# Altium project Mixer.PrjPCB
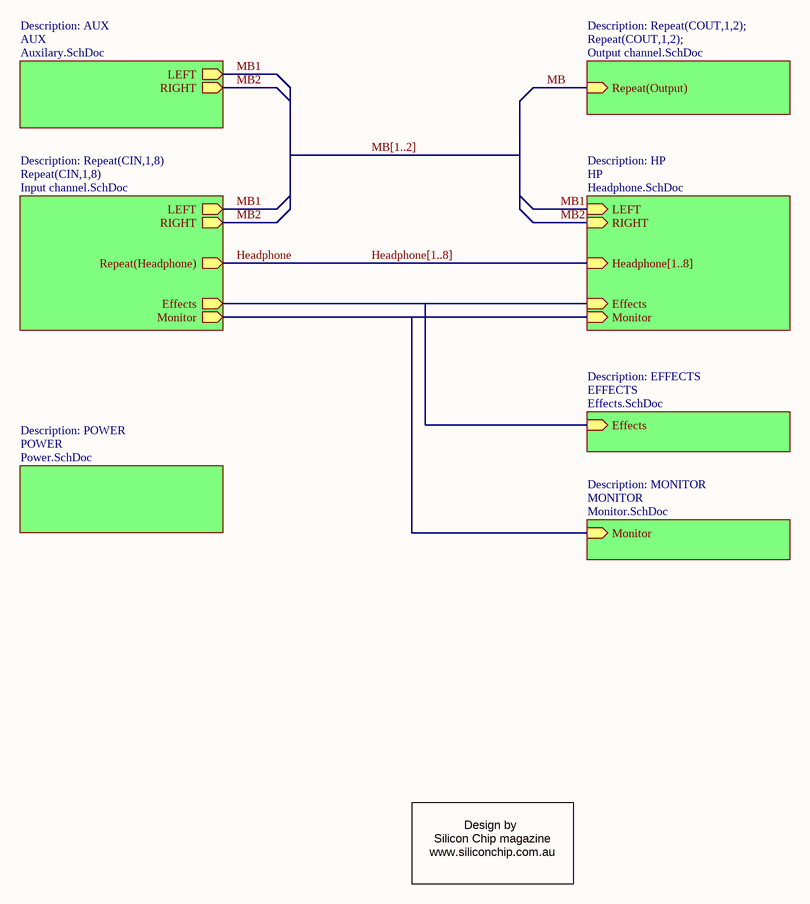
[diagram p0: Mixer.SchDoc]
8 sheets, 523 parts. Net scope: hierarchical (ports join the sheet entries above them; power ports are global).
Board files: Mixer_Blank.PCBDOC, Mixer_Loaded.PCBDOC, Mixer_Placed.PCBDOC, Mixer_RoomsOnly.PCBDOC, Mixer_Routed.PCBDOC
Sheets:
  Mixer.SchDoc
    AUX = Auxilary.SchDoc
    CIN1 = Input channel.SchDoc
    CIN2 = Input channel.SchDoc
    CIN3 = Input channel.SchDoc
    CIN4 = Input channel.SchDoc
    CIN5 = Input channel.SchDoc
    CIN6 = Input channel.SchDoc
    CIN7 = Input channel.SchDoc
    CIN8 = Input channel.SchDoc
    MONITOR = Monitor.SchDoc
    EFFECTS = Effects.SchDoc
    HP = Headphone.SchDoc
    POWER = Power.SchDoc
    Repeat(COUT,1,2); = Output channel.SchDoc

## Sheet Mixer.SchDoc
size A4; Organization: Altium Limited; Address1: L3, 12a Rodborough Rd; Address2: Frenchs Forest; Address3: NSW; Address4: Australia 2086; DocumentNumber: 5; SheetNumber: 5; SheetTotal: 8

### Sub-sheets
AUX = Auxilary.SchDoc: LEFT, RIGHT  | Description: AUX
EFFECTS = Effects.SchDoc: Effects  | Description: EFFECTS
HP = Headphone.SchDoc: Headphone[1..8] (in), Monitor, Effects, LEFT, RIGHT  | Description: HP
MONITOR = Monitor.SchDoc: Monitor  | Description: MONITOR
POWER = Power.SchDoc: no entries  | Description: POWER
Repeat(CIN,1,8) = Input channel.SchDoc: Monitor, LEFT, Repeat(Headphone) (out), Effects, RIGHT  | Description: Repeat(CIN,1,8)
Repeat(COUT,1,2); = Output channel.SchDoc: Repeat(Output)  | Description: Repeat(COUT,1,2);

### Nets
MB1: sheet AUX/LEFT, sheet Repeat(CIN,1,8)/LEFT, sheet HP/LEFT
MB2: sheet AUX/RIGHT, sheet Repeat(CIN,1,8)/RIGHT, sheet HP/RIGHT
NetR29_1: sheet Repeat(CIN,1,8)/Monitor, sheet MONITOR/Monitor, sheet HP/Monitor
NetR33_1: sheet Repeat(CIN,1,8)/Effects, sheet EFFECTS/Effects, sheet HP/Effects

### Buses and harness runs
bus Headphone[1..8] = sheet HP/Headphone[1..8]
bus MB[1..2]

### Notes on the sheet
- Design by
  Silicon Chip magazine
  www.siliconchip.com.au

## Sheet Auxilary.SchDoc
size A4; Organization: Altium Limited; Address1: L3, 12a Rodborough Rd; Address2: Frenchs Forest; Address3: NSW; Address4: Australia 2086; DocumentNumber: 1; SheetNumber: 1; SheetTotal: 8
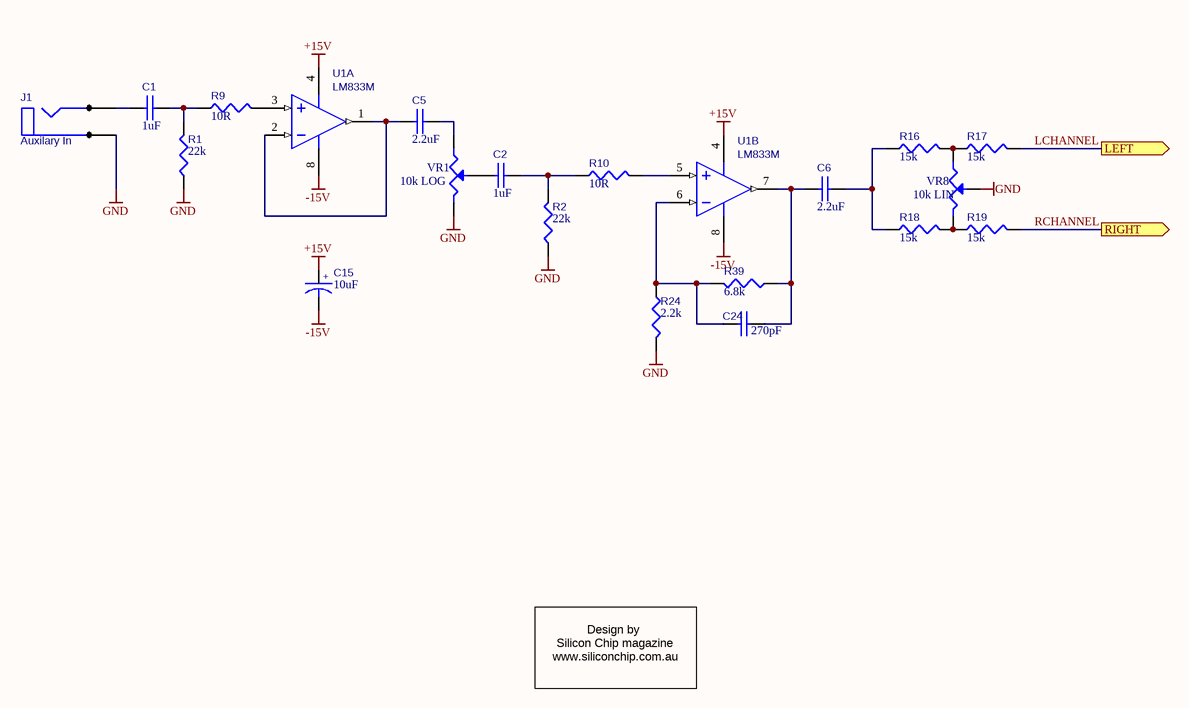
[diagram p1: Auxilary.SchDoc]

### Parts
C1  1uF  [RB.2/.4-NP]
C2  1uF  [RB.2/.4-NP]
C5  2.2uF  [RB.2/.4-NP]
C6  2.2uF  [RB.2/.4-NP]
C15  10uF  [RB.2/.4]
C24  270pF  [RAD0.2]
J1  Auxilary In  [JACK-6.25MM]
R1  22k  [AXIAL0.4]
R2  22k  [AXIAL0.4]
R9  10R  [AXIAL0.4]
R10  10R  [AXIAL0.4]
R16  15k  [AXIAL0.4]
R17  15k  [AXIAL0.4]
R18  15k  [AXIAL0.4]
R19  15k  [AXIAL0.4]
R24  2.2k  [AXIAL0.4]
R39  6.8k  [AXIAL0.4]
U1  LM833M  [DIP8]  (parts A,B of 2)
VR1  10k LOG  [POT - 24MM]
VR8  10k LIN  [POT - 24MM]

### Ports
LEFT (out), RIGHT (out)

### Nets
+15V: C15.1 U1.4(V-)
-15V: C15.2 U1.8(V+)
GND: J1.3(C) R1.1 R2.1 R24.2 VR1.3 VR8.2(W)
LCHANNEL: R17.2 ; port LEFT  [project net MB1]
RCHANNEL: R19.2 ; port RIGHT  [project net MB2]
NetC1_1: C1.1 J1.1(A)
NetC1_2: C1.2 R1.2 R9.1
NetC2_1: C2.1 VR1.2(W)
NetC2_2: C2.2 R2.2 R10.1
NetC5_1: C5.1 U1.1(OUT1) U1.2(IN1-)
NetC5_2: C5.2 VR1.1
NetC6_1: C6.1 C24.2 R39.1 U1.7(OUT2)
NetC6_2: C6.2 R16.1 R18.1
NetC24_1: C24.1 R24.1 R39.2 U1.6(IN2-)
NetR9_2: R9.2 U1.3(IN1+)
NetR10_2: R10.2 U1.5(IN2+)
NetR16_2: R16.2 R17.1 VR8.1
NetR18_2: R18.2 R19.1 VR8.3

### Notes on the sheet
- Design by
  Silicon Chip magazine
  www.siliconchip.com.au

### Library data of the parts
C1 C2 C5 C6 C24 = CAP: Capacitor
C15 = CAPACITOR POL: Bi-Polar Capacitor
J1 = PHONEJACK MONO
R1 R2 R9 R10 R16-R19 R24 R39 = RES1: Resistor
U1 = LM833M: Fast Settling Dual Operational Amplifier
VR1 VR8 = POT1: Potentiometer

## Sheet Input channel.SchDoc
size A4; Organization: Altium Limited; Address1: L3, 12a Rodborough Rd; Address2: Frenchs Forest; Address3: NSW; Address4: Australia 2086; DocumentNumber: 4; SheetNumber: 4; SheetTotal: 8
Used 8 times, as channels CIN1, CIN2, CIN3, CIN4, CIN5, CIN6, CIN7, CIN8. Parts and nets are listed once, with the designators drawn on the sheet.
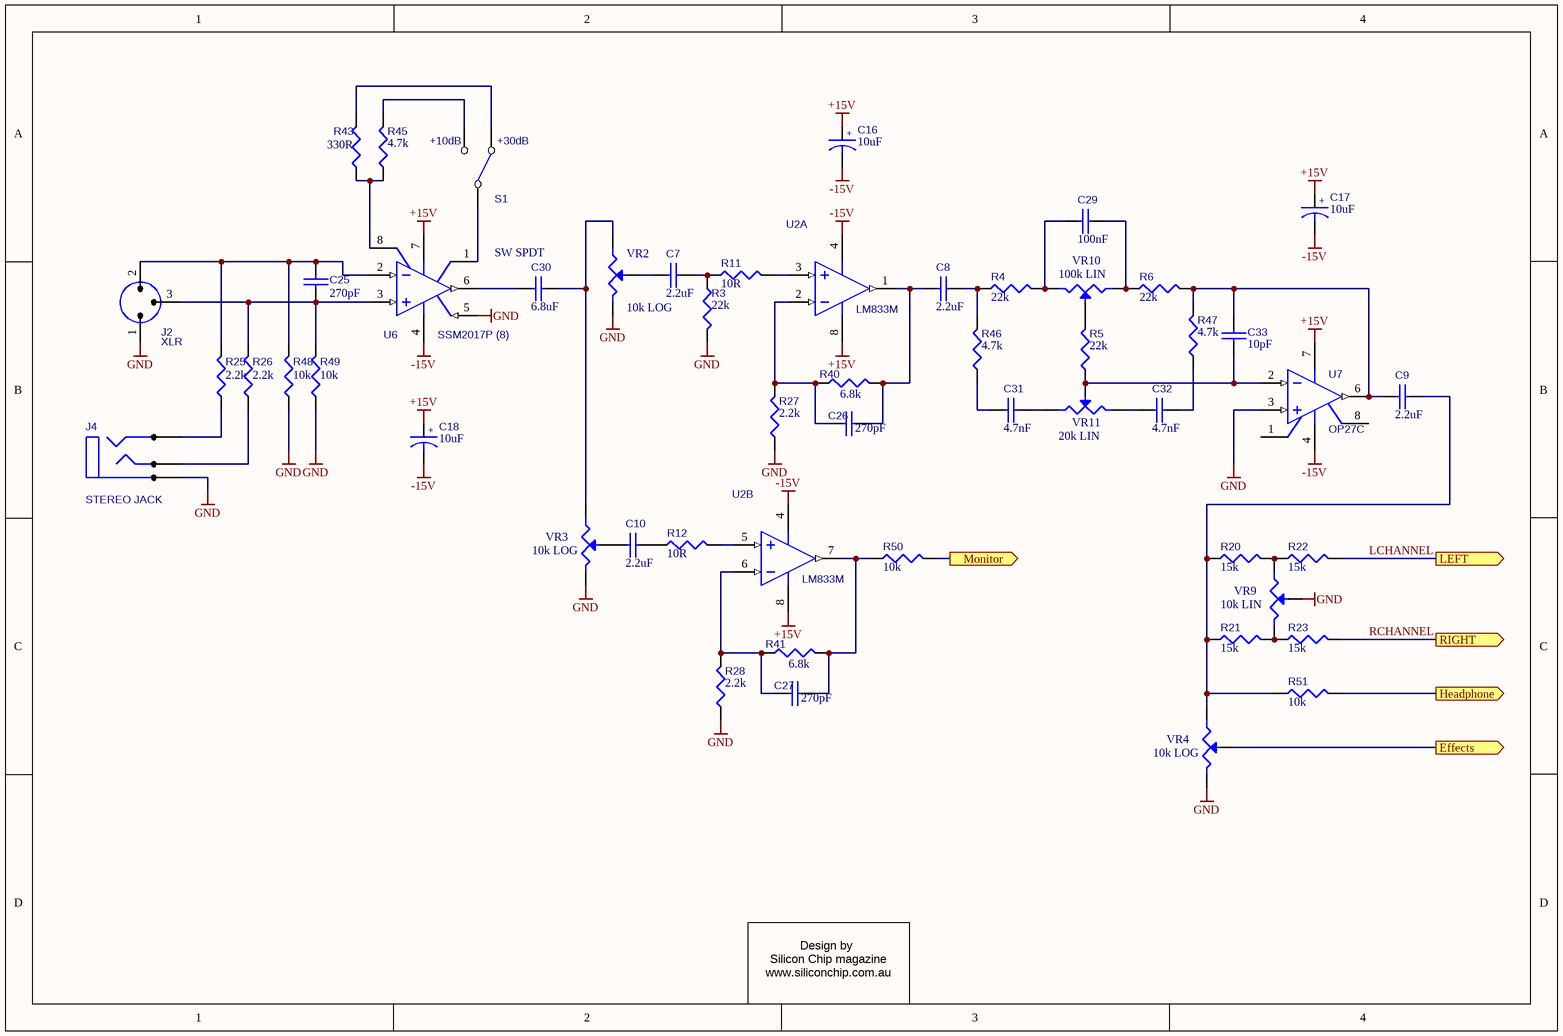
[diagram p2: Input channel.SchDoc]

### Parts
C7  2.2uF  [RB.2/.4-NP]
C8  2.2uF  [RB.2/.4-NP]
C9  2.2uF  [RB.2/.4-NP]
C10  2.2uF  [RB.2/.4-NP]
C16  10uF  [RB.2/.4]
C17  10uF  [RB.2/.4]
C18  10uF  [RB.2/.4]
C25  270pF  [RAD0.2]
C26  270pF  [RAD0.2]
C27  270pF  [RAD0.2]
C29  100nF  [RAD0.2]
C30  6.8uF  [RB.2/.4-NP]
C31  4.7nF  [RAD0.2]
C32  4.7nF  [RAD0.2]
C33  10pF  [RAD0.2]
J2  XLR  [XLR-FEMALE]
J4  STEREO JACK  [JACK-6.25MM]
R3  22k  [AXIAL0.4]
R4  22k  [AXIAL0.4]
R5  22k  [AXIAL0.4]
R6  22k  [AXIAL0.4]
R11  10R  [AXIAL0.4]
R12  10R  [AXIAL0.4]
R20  15k  [AXIAL0.4]
R21  15k  [AXIAL0.4]
R22  15k  [AXIAL0.4]
R23  15k  [AXIAL0.4]
R25  2.2k  [AXIAL0.4]
R26  2.2k  [AXIAL0.4]
R27  2.2k  [AXIAL0.4]
R28  2.2k  [AXIAL0.4]
R40  6.8k  [AXIAL0.4]
R41  6.8k  [AXIAL0.4]
R43  330R  [AXIAL0.4]
R45  4.7k  [AXIAL0.4]
R46  4.7k  [AXIAL0.4]
R47  4.7k  [AXIAL0.4]
R48  10k  [AXIAL0.4]
R49  10k  [AXIAL0.4]
R50  10k  [AXIAL0.4]
R51  10k  [AXIAL0.4]
S1  SW SPDT  [SW-SPDT]
U2  LM833M  [DIP8]  (parts A,B of 2)
U6  SSM2017P (8)  [DIP8]
U7  OP27C  [DIP8]
VR2  10k LOG  [POT - 24MM]
VR3  10k LOG  [POT - 24MM]
VR4  10k LOG  [POT - 24MM]
VR9  10k LIN  [POT - 24MM]
VR10  100k LIN  [POT - 24MM]
VR11  20k LIN  [POT - 24MM]

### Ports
Effects (out), Headphone (out), LEFT (out), Monitor (out), RIGHT (out)

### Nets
+15V: C16.1 C17.1 C18.1 U2.8(V+) U6.7(V+) U7.7(V+)
-15V: C16.2 C17.2 C18.2 U2.4(V-) U6.4(V-) U7.4(V-)
GND: J2.1 J4.3(C) R3.2 R27.1 R28.1 R48.1 R49.1 U6.5(REF) U7.3(+IN) VR2.3 VR3.3 VR4.3 VR9.2(W)
Effects: VR4.2(W) ; port Effects
Headphone: R51.2 ; port Headphone
LCHANNEL: R22.2 ; port LEFT
Monitor: R50.2 ; port Monitor
RCHANNEL: R23.2 ; port RIGHT
NetC7_1: C7.1 VR2.2(W)
NetC7_2: C7.2 R3.1 R11.1
NetC8_1: C8.1 C26.2 R40.2 U2.1(OUT1)
NetC8_2: C8.2 R4.1 R46.2
NetC9_1: C9.1 C33.2 R6.2 R47.2 U7.6(OUT)
NetC9_2: C9.2 R20.1 R21.1 R51.1 VR4.1
NetC10_1: C10.1 VR3.2(W)
NetC10_2: C10.2 R12.1
NetC25_1: C25.1 J2.2 R25.2 R48.2 U6.2(IN-)
NetC25_2: C25.2 J2.3 R26.2 R49.2 U6.3(IN+)
NetC26_1: C26.1 R27.2 R40.1 U2.2(IN1-)
NetC27_1: C27.1 R28.2 R41.1 U2.6(IN2-)
NetC27_2: C27.2 R41.2 R50.1 U2.7(OUT2)
NetC29_1: C29.1 R4.2 VR10.3
NetC29_2: C29.2 R6.1 VR10.1
NetC30_1: C30.1 U6.6(OUT)
NetC30_2: C30.2 VR2.1 VR3.1
NetC31_1: C31.1 R46.1
NetC31_2: C31.2 VR11.1
NetC32_1: C32.1 VR11.3
NetC32_2: C32.2 R47.1
NetC33_1: C33.1 R5.1 U7.2(-IN) VR11.2(W)
NetJ4_1: J4.1(A) R25.1
NetJ4_2: J4.2(B) R26.1
NetR5_2: R5.2 VR10.2(W)
NetR11_2: R11.2 U2.3(IN1+)
NetR12_2: R12.2 U2.5(IN2+)
NetR20_2: R20.2 R22.1 VR9.1
NetR21_2: R21.2 R23.1 VR9.3
NetR43_1: R43.1 R45.1 U6.8(RG2)
NetR43_2: R43.2 S1.2(NC)
NetR45_2: R45.2 S1.3(NO)
NetS1_1: S1.1(COMMON) U6.1(RG1)

Not connected (* = marked no-connect by the designer): U7 1(TRIM) 8(TRIM)

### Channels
CIN1: designators end in _CIN1; ports Effects=NetR33_1 Headphone=Headphone1 LEFT=MB1 Monitor=NetR29_1 RIGHT=MB2
CIN2: designators end in _CIN2; ports Effects=NetR33_1 Headphone=Headphone2 LEFT=MB1 Monitor=NetR29_1 RIGHT=MB2
CIN3: designators end in _CIN3; ports Effects=NetR33_1 Headphone=Headphone3 LEFT=MB1 Monitor=NetR29_1 RIGHT=MB2
CIN4: designators end in _CIN4; ports Effects=NetR33_1 Headphone=Headphone4 LEFT=MB1 Monitor=NetR29_1 RIGHT=MB2
CIN5: designators end in _CIN5; ports Effects=NetR33_1 Headphone=Headphone5 LEFT=MB1 Monitor=NetR29_1 RIGHT=MB2
CIN6: designators end in _CIN6; ports Effects=NetR33_1 Headphone=Headphone6 LEFT=MB1 Monitor=NetR29_1 RIGHT=MB2
CIN7: designators end in _CIN7; ports Effects=NetR33_1 Headphone=Headphone7 LEFT=MB1 Monitor=NetR29_1 RIGHT=MB2
CIN8: designators end in _CIN8; ports Effects=NetR33_1 Headphone=Headphone8 LEFT=MB1 Monitor=NetR29_1 RIGHT=MB2

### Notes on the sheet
- (near S1) +10dB
- (near S1) +30dB
- Design by
  Silicon Chip magazine
  www.siliconchip.com.au

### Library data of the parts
C7-C10 C25-C27 C29-C33 = CAP: Capacitor
C16-C18 = CAPACITOR POL: Bi-Polar Capacitor
J2 = XLR: XLR connector, PCB mounted
J4 = PHONEJACK STEREO
R3-R6 R11 R12 R20-R23 R25-R28 R40 R41 R43 R45-R51 = RES1: Resistor
U2 = LM833M: Fast Settling Dual Operational Amplifier
U6 = SSM2017P (8): Self-Contained Audio Preamplifier
U7 = OP27C: Low Noise, High Speed Precision Operational Amplifier
VR2-VR4 VR9-VR11 = POT1: Potentiometer

## Sheet Monitor.SchDoc
size A4; Organization: Altium Limited; Address1: L3, 12a Rodborough Rd; Address2: Frenchs Forest; Address3: NSW; Address4: Australia 2086; DocumentNumber: 6; SheetNumber: 6; SheetTotal: 8
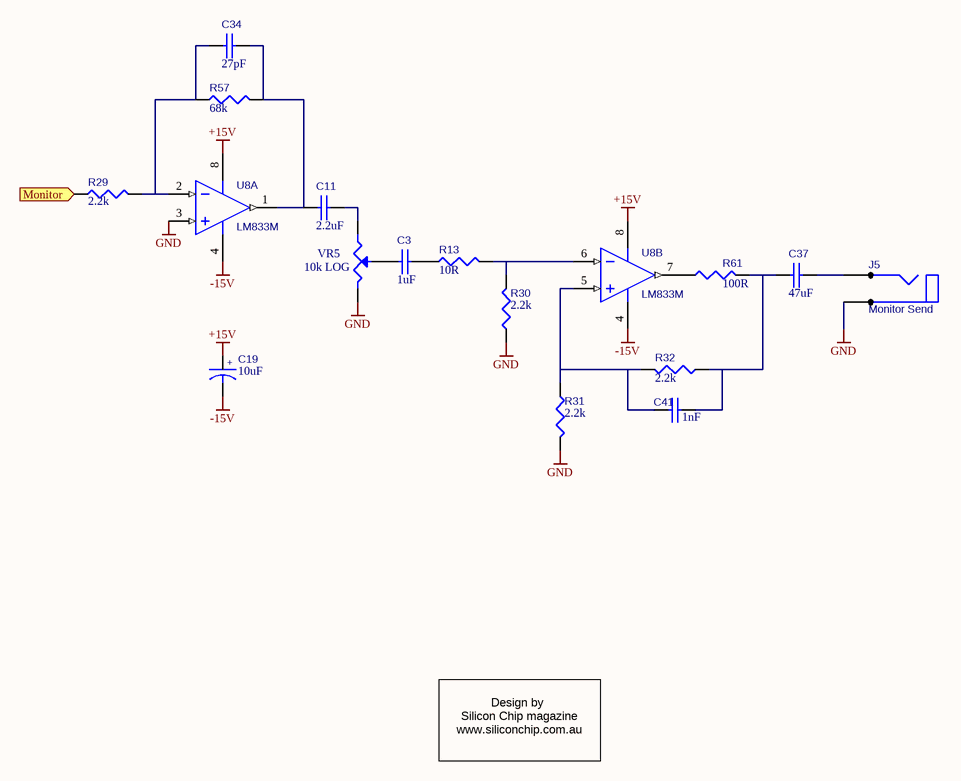
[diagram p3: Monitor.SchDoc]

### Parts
C3  1uF  [RB.2/.4-NP]
C11  2.2uF  [RB.2/.4-NP]
C19  10uF  [RB.2/.4]
C34  27pF  [RAD0.2]
C37  47uF  [RB.2/.4-NP]
C41  1nF  [RAD0.2]
J5  Monitor Send  [JACK-6.25MM]
R13  10R  [AXIAL0.4]
R29  2.2k  [AXIAL0.4]
R30  2.2k  [AXIAL0.4]
R31  2.2k  [AXIAL0.4]
R32  2.2k  [AXIAL0.4]
R57  68k  [AXIAL0.4]
R61  100R  [AXIAL0.4]
U8  LM833M  [DIP8]  (parts A,B of 2)
VR5  10k LOG  [POT - 24MM]

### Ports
Monitor (in)

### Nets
+15V: C19.1 U8.8(V+)
-15V: C19.2 U8.4(V-)
GND: J5.3(C) R30.1 R31.2 U8.3(IN1+) VR5.3
NetC3_1: C3.1 VR5.2(W)
NetC3_2: C3.2 R13.1
NetC11_1: C11.1 C34.2 R57.2 U8.1(OUT1)
NetC11_2: C11.2 VR5.1
NetC34_1: C34.1 R29.2 R57.1 U8.2(IN1-)
NetC37_1: C37.1 C41.2 R32.1 R61.2
NetC37_2: C37.2 J5.1(A)
NetC41_1: C41.1 R31.1 R32.2 U8.5(IN2+)
NetR13_2: R13.2 R30.2 U8.6(IN2-)
NetR29_1: R29.1 ; port Monitor
NetR61_1: R61.1 U8.7(OUT2)

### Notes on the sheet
- Design by
  Silicon Chip magazine
  www.siliconchip.com.au

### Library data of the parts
C3 C11 C34 C37 C41 = CAP: Capacitor
C19 = CAPACITOR POL: Bi-Polar Capacitor
J5 = PHONEJACK MONO
R13 R29-R32 R57 R61 = RES1: Resistor
U8 = LM833: Fast Settling Dual Operational Amplifier
VR5 = POT1: Potentiometer

## Sheet Effects.SchDoc
size A4; Organization: Altium Limited; Address1: L3, 12a Rodborough Rd; Address2: Frenchs Forest; Address3: NSW; Address4: Australia 2086; DocumentNumber: 2; SheetNumber: 2; SheetTotal: 8
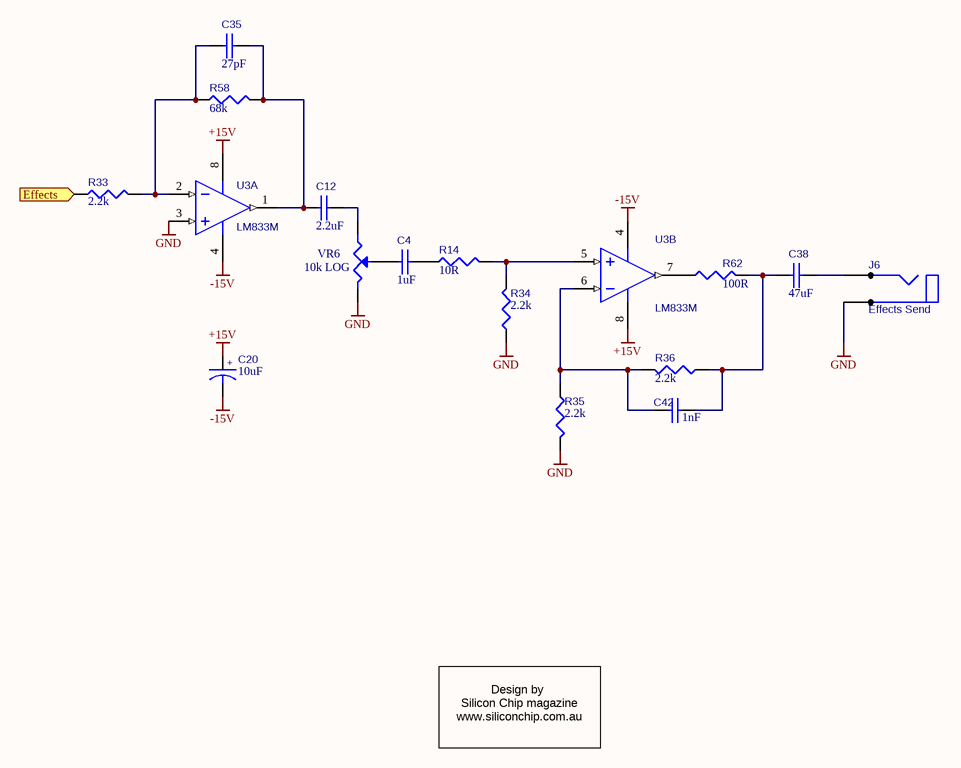
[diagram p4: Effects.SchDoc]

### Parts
C4  1uF  [RB.2/.4-NP]
C12  2.2uF  [RB.2/.4-NP]
C20  10uF  [RB.2/.4]
C35  27pF  [RAD0.2]
C38  47uF  [RB.2/.4-NP]
C42  1nF  [RAD0.2]
J6  Effects Send  [JACK-6.25MM]
R14  10R  [AXIAL0.4]
R33  2.2k  [AXIAL0.4]
R34  2.2k  [AXIAL0.4]
R35  2.2k  [AXIAL0.4]
R36  2.2k  [AXIAL0.4]
R58  68k  [AXIAL0.4]
R62  100R  [AXIAL0.4]
U3  LM833M  [DIP8]  (parts A,B of 2)
VR6  10k LOG  [POT - 24MM]

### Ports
Effects (in)

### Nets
+15V: C20.1 U3.8(V+)
-15V: C20.2 U3.4(V-)
GND: J6.3(C) R34.1 R35.2 U3.3(IN1+) VR6.3
NetC4_1: C4.1 VR6.2(W)
NetC4_2: C4.2 R14.1
NetC12_1: C12.1 C35.2 R58.2 U3.1(OUT1)
NetC12_2: C12.2 VR6.1
NetC35_1: C35.1 R33.2 R58.1 U3.2(IN1-)
NetC38_1: C38.1 C42.2 R36.1 R62.2
NetC38_2: C38.2 J6.1(A)
NetC42_1: C42.1 R35.1 R36.2 U3.6(IN2-)
NetR14_2: R14.2 R34.2 U3.5(IN2+)
NetR33_1: R33.1 ; port Effects
NetR62_1: R62.1 U3.7(OUT2)

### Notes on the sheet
- Design by
  Silicon Chip magazine
  www.siliconchip.com.au

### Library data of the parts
C4 C12 C35 C38 C42 = CAP: Capacitor
C20 = CAPACITOR POL: Bi-Polar Capacitor
J6 = PHONEJACK MONO
R14 R33-R36 R58 R62 = RES1: Resistor
U3 = LM833M: Fast Settling Dual Operational Amplifier
VR6 = POT1: Potentiometer

## Sheet Headphone.SchDoc
size A4; Organization: Altium Limited; Address1: L3, 12a Rodborough Rd; Address2: Frenchs Forest; Address3: NSW; Address4: Australia 2086; DocumentNumber: 3; SheetNumber: 3; SheetTotal: 8
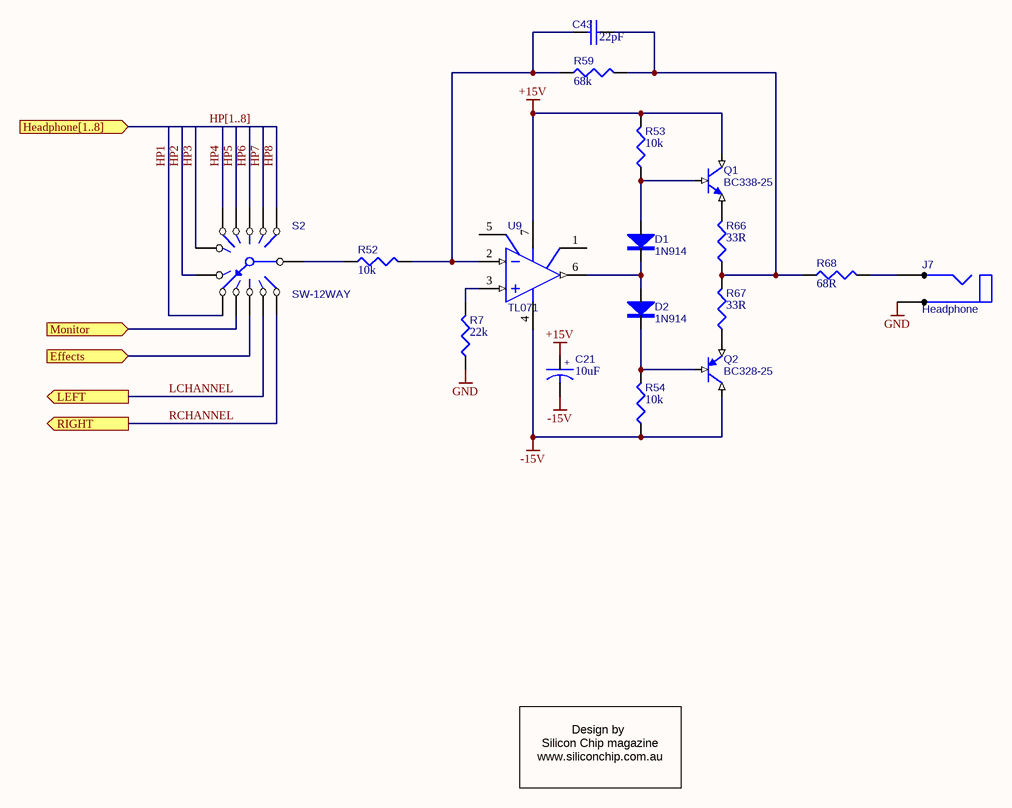
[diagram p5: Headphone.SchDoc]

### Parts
C21  10uF  [RB.2/.4]
C43  22pF  [RAD0.2]
D1  1N914  [DIODE0.4]
D2  1N914  [DIODE0.4]
J7  Headphone  [JACK-6.25MM]
Q1  BC338-25  [TO-92A]
Q2  BC328-25  [TO-92A]
R7  22k  [AXIAL0.4]
R52  10k  [AXIAL0.4]
R53  10k  [AXIAL0.4]
R54  10k  [AXIAL0.4]
R59  68k  [AXIAL0.4]
R66  33R  [AXIAL0.4]
R67  33R  [AXIAL0.4]
R68  68R  [AXIAL0.4]
S2  SW-12WAY  [SW-12WAY]
U9  TL071  [DIP8]

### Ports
Effects (in), Headphone[1..8] (in), LEFT (out), Monitor (in), RIGHT (out)

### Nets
+15V: C21.1 Q1.1(C) R53.2 U9.7(VCC+)
-15V: C21.2 Q2.1(C) R54.1 U9.4(VCC-)
GND: J7.3(C) R7.1
HP1: S2.8  [project net Headphone1]
HP2: S2.7  [project net Headphone2]
HP3: S2.6  [project net Headphone3]
HP4: S2.5  [project net Headphone4]
HP5: S2.4  [project net Headphone5]
HP6: S2.3  [project net Headphone6]
HP7: S2.2  [project net Headphone7]
HP8: S2.1  [project net Headphone8]
LCHANNEL: S2.11 ; port LEFT  [project net MB1]
RCHANNEL: S2.12 ; port RIGHT  [project net MB2]
NetC43_1: C43.1 R52.2 R59.1 U9.2(IN-)
NetC43_2: C43.2 R59.2 R66.1 R67.2 R68.1
NetD1_1: D1.1(A) Q1.2(B) R53.1
NetD1_2: D1.2(K) D2.1(A) U9.6(OUT)
NetD2_2: D2.2(K) Q2.2(B) R54.2
NetJ7_1: J7.1(A) R68.2
NetQ1_3: Q1.3(E) R66.2
NetQ2_3: Q2.3(E) R67.1
NetR7_2: R7.2 U9.3(IN+)
NetR29_1: S2.9 ; port Monitor
NetR33_1: S2.10 ; port Effects
NetR52_1: R52.1 S2.13

Not connected (* = marked no-connect by the designer): U9 1(N1/O.S.) 5(O.S._N2)

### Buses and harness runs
bus HP[1..8] = port Headphone[1..8]

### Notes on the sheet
- Design by
  Silicon Chip magazine
  www.siliconchip.com.au

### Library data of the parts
C21 = CAPACITOR POL: Bi-Polar Capacitor
C43 = CAP: Capacitor
D1 D2 = 1N914: Diode
J7 = PHONEJACK MONO
Q1 = BC338-25: NPN BJT
Q2 = BC328-25: PNP BJT
R7 R52-R54 R59 R66-R68 = RES1: Resistor
U9 = TL071: Low-Noise  JFET-Input Operational Amplifiers

## Sheet Power.SchDoc
size A4; Organization: Altium Limited; Address1: L3, 12a Rodborough Rd; Address2: Frenchs Forest; Address3: NSW; Address4: Australia 2086; DocumentNumber: 8; SheetNumber: 8; SheetTotal: 8
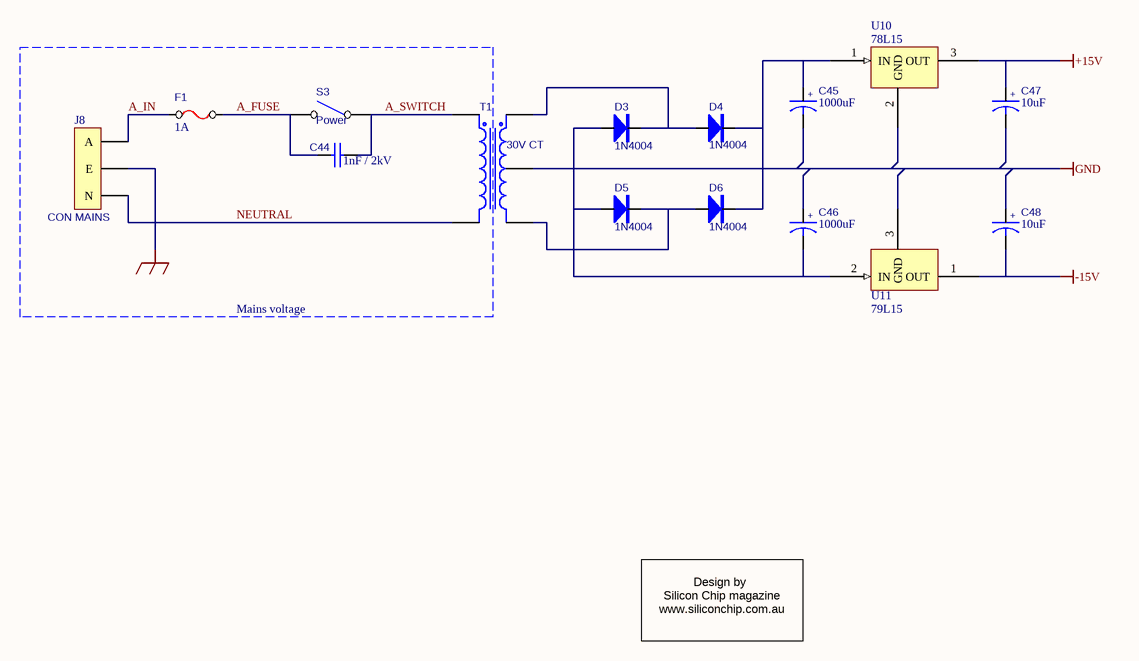
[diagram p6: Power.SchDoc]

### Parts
C44  1nF / 2kV  [RAD0.8]
C45  1000uF  [RB.4/.8]
C46  1000uF  [RB.4/.8]
C47  10uF  [RB.2/.4]
C48  10uF  [RB.2/.4]
D3  1N4004  [DIODE0.5]
D4  1N4004  [DIODE0.5]
D5  1N4004  [DIODE0.5]
D6  1N4004  [DIODE0.5]
F1  1A  [FUSE]
J8  CON MAINS  [IEC-MAINS]
S3  Power  [SW-MAINS]
T1  30V CT  [TRANSFORMER]
U10  78L15  [TO-92A]
U11  79L15  [TO-92A]

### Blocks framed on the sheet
Mains voltage: C44 F1 J8 S3

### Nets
+15V: C47.1 U10.3(OUT)
-15V: C48.2 U11.1(OUT)
CHASSIS: J8.2(E)
GND: C45.2 C46.1 C47.2 C48.1 T1.4(SecCT) U10.2(GND) U11.3(GND)
A_FUSE: C44.2 F1.2 S3.2(NO)
A_IN: F1.1 J8.1(A)
A_SWITCH: C44.1 S3.1(COMMON) T1.1(Pri+)
NEUTRAL: J8.3(N) T1.2(Pri-)
NetC45_1: C45.1 D4.2(K) D6.2(K) U10.1(IN)
NetC46_2: C46.2 D3.1(A) D5.1(A) U11.2(IN)
NetD3_2: D3.2(K) D4.1(A) T1.3(Sec+)
NetD5_2: D5.2(K) D6.1(A) T1.5(Sec-)

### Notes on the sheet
- Design by
  Silicon Chip magazine
  www.siliconchip.com.au

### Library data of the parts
C44 = CAP: Capacitor
C45-C48 = CAPACITOR POL: Bi-Polar Capacitor
D3-D6 = 1N4004: Diode
F1 = FUSE
J8 = CON MAINS: Connector
S3 = SW SPST
T1 = 30V CT: Center-Tapped Transformer
U10 = 78L15: Very Low Drop Voltage Regulators With Inhibit
U11 = 79L15: Very Low Drop Voltage Regulators With Inhibit

## Sheet Output channel.SchDoc
size A4; Organization: Altium Limited; Address1: L3, 12a Rodborough Rd; Address2: Frenchs Forest; Address3: NSW; Address4: Australia 2086; DocumentNumber: 7; SheetNumber: 7; SheetTotal: 8
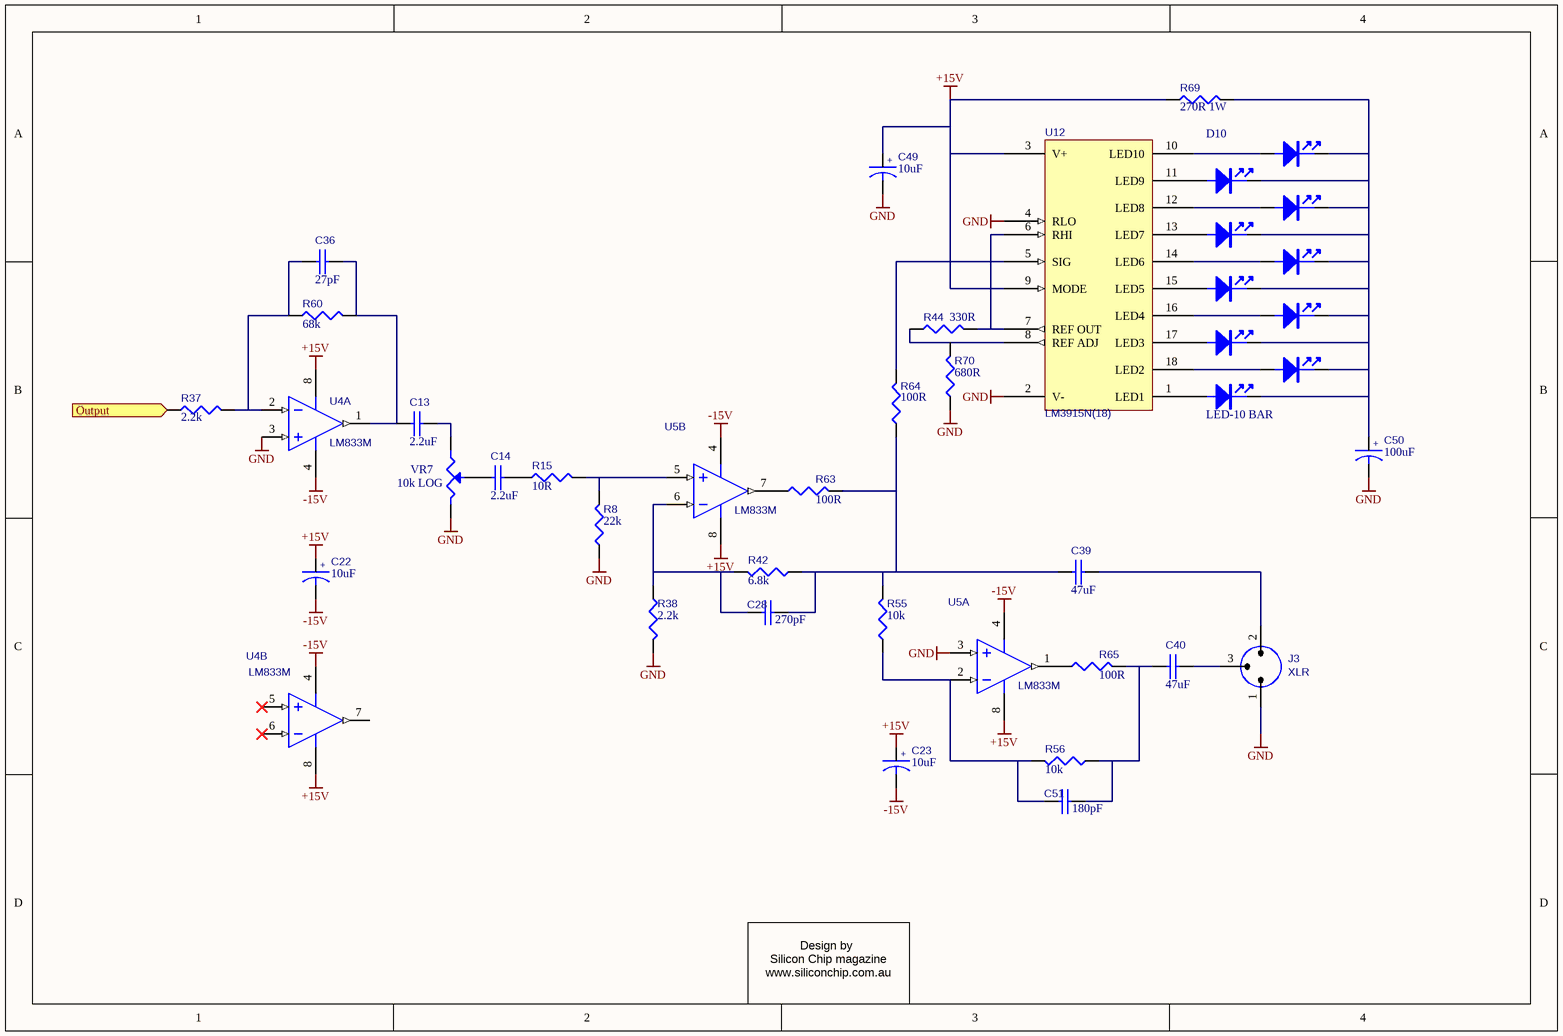
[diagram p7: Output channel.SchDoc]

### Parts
C13  2.2uF  [RB.2/.4-NP]
C14  2.2uF  [RB.2/.4-NP]
C22  10uF  [RB.2/.4]
C23  10uF  [RB.2/.4]
C28  270pF  [RAD0.2]
C36  27pF  [RAD0.2]
C39  47uF  [RB.2/.4-NP]
C40  47uF  [RB.2/.4-NP]
C49  10uF  [RB.2/.4]
C50  100uF  [RB.2/.4]
C51  180pF  [RAD0.2]
D10  LED-10 BAR  [LED - 10 BAR HORIZONTAL]
J3  XLR  [XLR-MALE]
R8  22k  [AXIAL0.4]
R15  10R  [AXIAL0.4]
R37  2.2k  [AXIAL0.4]
R38  2.2k  [AXIAL0.4]
R42  6.8k  [AXIAL0.4]
R44  330R  [AXIAL0.4]
R55  10k  [AXIAL0.4]
R56  10k  [AXIAL0.4]
R60  68k  [AXIAL0.4]
R63  100R  [AXIAL0.4]
R64  100R  [AXIAL0.4]
R65  100R  [AXIAL0.4]
R69  270R 1W  [AXIAL0.4]
R70  680R  [AXIAL0.4]
U4  LM833M  [DIP8]  (parts A,B of 2)
U5  LM833M  [DIP8]  (parts A,B of 2)
U12  LM3915N(18)  [DIP18]
VR7  10k LOG  [POT - 24MM]

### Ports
Output (in)

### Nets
+15V: C22.1 C23.1 C49.1 R69.1 U4.8(V+) U5.8(V+) U12.3(V+) U12.9(MODE)
-15V: C22.2 C23.2 U4.4(V-) U5.4(V-)
GND: C49.2 C50.2 J3.1 R8.1 R38.2 R70.1 U4.3(IN1+) U5.3(IN1+) U12.2(V-) U12.4(RLO) VR7.3
MB: R37.1 ; port Output
NetC13_1: C13.1 C36.2 R60.2 U4.1(OUT1)
NetC13_2: C13.2 VR7.1
NetC14_1: C14.1 VR7.2(W)
NetC14_2: C14.2 R15.1
NetC28_1: C28.1 R38.1 R42.2 U5.6(IN2-)
NetC28_2: C28.2 C39.1 R42.1 R55.2 R63.2 R64.1
NetC36_1: C36.1 R37.2 R60.1 U4.2(IN1-)
NetC39_2: C39.2 J3.2
NetC40_1: C40.1 C51.2 R56.1 R65.2
NetC40_2: C40.2 J3.3
NetC50_1: C50.1 D10.2(K) D10.4(K) D10.6(K) D10.8(K) D10.10(K) D10.12(K) D10.14(K) D10.16(K) D10.18(K) D10.20(K) R69.2
NetC51_1: C51.1 R55.1 R56.2 U5.2(IN1-)
NetD10_1: D10.1(A) U12.1(LED1)
NetD10_3: D10.3(A) U12.18(LED2)
NetD10_5: D10.5(A) U12.17(LED3)
NetD10_7: D10.7(A) U12.16(LED4)
NetD10_9: D10.9(A) U12.15(LED5)
NetD10_11: D10.11(A) U12.14(LED6)
NetD10_13: D10.13(A) U12.13(LED7)
NetD10_15: D10.15(A) U12.12(LED8)
NetD10_17: D10.17(A) U12.11(LED9)
NetD10_19: D10.19(A) U12.10(LED10)
NetR8_2: R8.2 R15.2 U5.5(IN2+)
NetR44_1: R44.1 R70.2 U12.8(REF_ADJ)
NetR44_2: R44.2 U12.6(RHI) U12.7(REF_OUT)
NetR63_1: R63.1 U5.7(OUT2)
NetR64_2: R64.2 U12.5(SIG)
NetR65_1: R65.1 U5.1(OUT1)

Not connected (* = marked no-connect by the designer): U4 5(IN2+)* 6(IN2-)* 7(OUT2)

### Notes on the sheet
- Design by
  Silicon Chip magazine
  www.siliconchip.com.au

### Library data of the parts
C13 C14 C28 C36 C39 C40 C51 = CAP: Capacitor
C22 C23 C49 C50 = CAPACITOR POL: Bi-Polar Capacitor
J3 = XLR: XLR connector, PCB mounted
R8 R15 R37 R38 R42 R44 R55 R56 R60 R63-R65 R69 R70 = RES1: Resistor
U4 U5 = LM833M: Fast Settling Dual Operational Amplifier
U12 = LM3915N(18): Dot/Bar Display Driver
VR7 = POT1: Potentiometer

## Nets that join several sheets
+15V: Auxilary (C15.1 U1.4), CIN1 (6 pins), CIN2 (6 pins), CIN3 (6 pins), CIN4 (6 pins), CIN5 (6 pins), CIN6 (6 pins), CIN7 (6 pins), CIN8 (6 pins), Monitor (C19.1 U8.8), Effects (C20.1 U3.8), Headphone (C21.1 Q1.1 R53.2 U9.7), Power (C47.1 U10.3), Output channel (8 pins)
-15V: Auxilary (C15.2 U1.8), CIN1 (6 pins), CIN2 (6 pins), CIN3 (6 pins), CIN4 (6 pins), CIN5 (6 pins), CIN6 (6 pins), CIN7 (6 pins), CIN8 (6 pins), Monitor (C19.2 U8.4), Effects (C20.2 U3.4), Headphone (C21.2 Q2.1 R54.1 U9.4), Power (C48.2 U11.1), Output channel (C22.2 C23.2 U4.4 U5.4)
GND: Auxilary (6 pins), CIN1 (13 pins), CIN2 (13 pins), CIN3 (13 pins), CIN4 (13 pins), CIN5 (13 pins), CIN6 (13 pins), CIN7 (13 pins), CIN8 (13 pins), Monitor (5 pins), Effects (5 pins), Headphone (J7.3 R7.1), Power (7 pins), Output channel (11 pins)
Headphone1: CIN1 (R51_CIN1.2), Headphone (S2.8)
Headphone2: CIN2 (R51_CIN2.2), Headphone (S2.7)
Headphone3: CIN3 (R51_CIN3.2), Headphone (S2.6)
Headphone4: CIN4 (R51_CIN4.2), Headphone (S2.5)
Headphone5: CIN5 (R51_CIN5.2), Headphone (S2.4)
Headphone6: CIN6 (R51_CIN6.2), Headphone (S2.3)
Headphone7: CIN7 (R51_CIN7.2), Headphone (S2.2)
Headphone8: CIN8 (R51_CIN8.2), Headphone (S2.1)
MB1: Auxilary (R17.2), CIN1 (R22_CIN1.2), CIN2 (R22_CIN2.2), CIN3 (R22_CIN3.2), CIN4 (R22_CIN4.2), CIN5 (R22_CIN5.2), CIN6 (R22_CIN6.2), CIN7 (R22_CIN7.2), CIN8 (R22_CIN8.2), Headphone (S2.11)
MB2: Auxilary (R19.2), CIN1 (R23_CIN1.2), CIN2 (R23_CIN2.2), CIN3 (R23_CIN3.2), CIN4 (R23_CIN4.2), CIN5 (R23_CIN5.2), CIN6 (R23_CIN6.2), CIN7 (R23_CIN7.2), CIN8 (R23_CIN8.2), Headphone (S2.12)
NetR29_1: CIN1 (R50_CIN1.2), CIN2 (R50_CIN2.2), CIN3 (R50_CIN3.2), CIN4 (R50_CIN4.2), CIN5 (R50_CIN5.2), CIN6 (R50_CIN6.2), CIN7 (R50_CIN7.2), CIN8 (R50_CIN8.2), Monitor (R29.1), Headphone (S2.9)
NetR33_1: CIN1 (VR4_CIN1.2), CIN2 (VR4_CIN2.2), CIN3 (VR4_CIN3.2), CIN4 (VR4_CIN4.2), CIN5 (VR4_CIN5.2), CIN6 (VR4_CIN6.2), CIN7 (VR4_CIN7.2), CIN8 (VR4_CIN8.2), Effects (R33.1), Headphone (S2.10)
